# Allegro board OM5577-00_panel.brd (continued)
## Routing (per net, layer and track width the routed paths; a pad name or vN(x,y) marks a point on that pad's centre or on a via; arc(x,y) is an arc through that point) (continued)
A_5_I2C_SCL: length 42.9
  IS1 w0.15: v3(216.2,175.8) 216.2,175.65 217.2,174.65 220.65,174.65 v2(221.2,174.1)
  IS2 w0.5: A_5_TB3.2 197.66,178.24 198.6,177.3 198.6,176.05 201.3,173.35 220.45,173.35 v2(221.2,174.1) 226.9,174.1 229.01,176.21 A_5_TB2.2
A_5_I2C_SDA: length 39
  TOP w0.2: v2(217.3,175.4) 217.3,175.6 216.6,176.3 A_5_U1.C1
  IS2 w0.5: A_5_TB3.3 198.57,180.78 204.1,175.25 210.7,175.25 210.95,175.5 217.2,175.5 v2(217.3,175.4) 219.5,175.4 220,174.9 223.55,174.9 227.4,178.75 A_5_TB2.3
A_5_IRQ: length 39.8
  TOP w0.2: v2(217.3,176.6) 217.3,176.5 217,176.8 A_5_U1.D1
  IS2 w0.5: A_5_TB3.4 198.63,183.32 205,176.95 210.8,176.95 211.25,176.5 217.2,176.5 v2(217.3,176.6) 217.4,176.5 219.8,176.5 220.35,175.95 222.5,175.95 227.84,181.29 A_5_TB2.4
A_5_N2189999: length 7.7
  TOP w0.5: A_5_R55.1 A_5_C17.1 A_5_C50.1 217.1,187.8 217.1,186.27 ; A_5_R53.2 A_5_C15.2 217.1,186.27 ; 217.1,186.27 A_5_C54.2
A_5_N2190055: length 7.8
  TOP w0.5: 212.3,186.27 212.3,187.8 A_5_C51.2 A_5_C18.2 A_5_R56.1 ; 212.3,186.27 A_5_C55.2 ; 212.3,186.27 A_5_C16.2 A_5_R54.2
A_5_N2190079: length 6.3
  TOP w0.5: A_5_C54.1 217.15,184.7 ; 217.15,184.7 217.15,183.1 A_5_R1.1 A_5_C13.1 217.04,181.56 A_5_L1.2 ; 217.15,184.7 A_5_C15.1
A_5_N2190159: length 11.7
  TOP w0.5: A_5_TB1.3 210.59,194.2 A_5_R73.1 arc(209.64,191.93) A_5_R56.2 arc(209.04,188.9) 208.95,188.42 A_5_C12.2 A_5_C52.2
A_5_N2190199: length 11.7
  TOP w0.5: A_5_C53.2 A_5_C11.2 220.45,188.42 arc(220.36,188.9) A_5_R55.2 arc(219.76,191.93) A_5_R75.1 218.81,194.2 A_5_TB1.1
A_5_N2190513: length 6.3
  TOP w0.5: 212.25,184.7 A_5_C16.1 ; 212.25,184.7 212.25,183.2 A_5_R2.2 212.37,181.65 A_5_C14.2 212.36,181.54 A_5_L2.2 ; 212.25,184.7 A_5_C55.1
A_5_N2190991: length 583.3
  TOP w0.5: A_5_L104.1 234.5,194.7 234.5,234.2 216.3,234.2 v2(216.3,234.15) ; A_5_L104.2 195,194.7 195,234.2 214.95,234.2 215.95,233.3 233.75,233.3 233.75,195.6 v2(214.7,195.6) ; v2(216.3,232.4) 233,232.4 233,196.5 214.45,196.5 213.45,195.6 195.75,195.6 195.75,233.3 v2(214.7,233.3) ; v2(214.7,231.5) 197.25,231.5 197.25,197.4 232.25,197.4 232.25,231.5 216.05,231.5 215.05,232.4 196.5,232.4 196.5,196.5 v2(213.1,196.5)
  BOTTOM w0.5: v2(214.7,233.3) v2(216.3,234.15) ; v2(216.3,232.4) v2(214.7,231.5) ; v2(214.7,195.6) v2(213.1,196.5)
A_5_N2198580: length 7.5
  TOP w0.2: A_5_R24.2 219.21,174.67 ; 219.21,174.67 A_5_R23.1 ; 219.21,174.67 219.24,174.7 219.7,174.7 220.1,174.3 v2(220.1,174.1)
  IS1 w0.15: v2(220.1,174.1) 217.25,174.1 215.7,175.65 v3(215.7,175.8)
A_5_N2222470: length 3.3
  TOP w0.5: A_5_R54.1 210.7,184.7 210.7,183.2 A_5_R2.1 A_5_C20.2
A_5_N2227379: length 3.3
  TOP w0.5: A_5_C19.2 A_5_R1.2 218.7,183.1 218.7,184.7 A_5_R53.1
A_5_N2256986: length 4.6
  TOP w0.25: A_5_Y1.3 215.22,172.28 215.5,172.55 215.65,172.55 215.95,172.85 216.29,172.85 A_5_C57.1 216.45,173.65 215.75,174.35 215.45,174.35 215.2,174.6 A_5_U1.A3
A_5_N2256988: length 4.4
  TOP w0.25: v2(214.18,174.53) 214.18,173.57 214.11,173.51 A_5_C56.1
  IS1 w0.25: v2(214.18,174.53) 214.7,175.05 214.7,175.65 215.2,176.15 v3(215.2,176.3)
A_5_N2257197: length 1.7
  TOP w0.2: A_5_U1.A1 216.99,174.51 A_5_R32.2
A_5_N2257995: length 4.2
  TOP w0.25: v2(212.7,174.7) 212.45,174.45 212.06,174.45 A_5_C22.1 A_5_C1.1
  IS1 w0.25: v3(213.7,176.3) 213.3,176.3 212.7,175.7 v2(212.7,174.7)
A_5_N2259746: length 5
  TOP w0.25: A_5_U1.E7 A_5_C7.1 211.91,177.89 211.8,178 209.14,178 A_5_C10.1
A_5_N2259753: length 1.5
  TOP w0.25: A_5_U1.D7 212.75,176.8 212.35,176.4 212.01,176.4 A_5_C8.1
A_5_N2259760: length 1.9
  TOP w0.25: A_5_C6.1 212.35,178.7 212.55,178.5 212.55,178.1 212.85,177.8 A_5_U1.F7
A_5_PVDD: length 62.1
  TOP w0.2: A_5_R23.2 A_5_C3.1
  TOP w0.25: A_5_U1.G1 216.5,178.3 216.9,178.7 A_5_C21.1 A_5_C9.1 ; A_5_U1.C7 212.95,176.3 212.65,176 212.65,175.6 212.35,175.3 A_5_C2.1
  TOP w0.3: A_5_U1.G2 A_5_U1.G1
  TOP w0.5: v2(222.35,172.9) 222.35,176.7 221.35,177.7 v2(220.7,177.7)
  IS1 w0.25: v3(215.2,176.8) 216.6,176.8 216.99,177.19 217.54,177.19 217.88,176.84 217.88,176.76 217.95,176.7 v3(218.05,176.7) v3(218.35,176.7)
  IS1 w0.3: v3(218.35,176.7) 218.35,177.4 218.05,177.7 v3(217.65,177.7) v3(217.35,177.7) ; v2(209.05,171.65) 209.05,174.9 209.65,175.5 v3(211.75,175.5) v3(211.75,175.1)
  IS1 w0.5: v2(220.7,177.7) 220.55,177.7 219.55,176.7 v3(218.35,176.7)
  IS2 w0.5: A_5_TB3.1 200.85,171.65 v2(209.05,171.65) 221.1,171.65 v2(222.35,172.9) 229.16,172.9 A_5_TB2.1
A_5_RXN: length 7.5
  TOP w0.5: A_5_C20.1 210.16,180.11 209.66,179.61 209.66,179.55 v2(209.66,179.55)
  IS1 w0.15: v2(209.66,179.55) 209.66,179.05 210.96,177.75 213.13,177.75 213.58,178.2 214,178.2 214.2,178 v3(214.2,177.8)
A_5_RXP: length 9
  TOP w0.5: v2(219.85,179.6) 219.39,180.06 218.6,180.06
  IS1 w0.15: v2(219.85,179.6) 218.95,178.7 216.4,178.7 215.9,178.2 214.95,178.2 214.7,177.95 214.7,177.6 214.5,177.4 213.9,177.4 213.7,177.6 v3(213.7,177.8)
A_5_TX1: length 1.8
  TOP w0.2: A_5_U1.G3 215.46,178.86
  TOP w0.25: 215.46,178.86 215.47,179.25
  TOP w0.5: 215.47,179.25 A_5_L1.1
A_5_TX2: length 1.8
  TOP w0.2: A_5_U1.G5 213.94,178.86
  TOP w0.25: 213.94,178.86 213.93,179.25
  TOP w0.5: 213.93,179.25 A_5_L2.1
A_5_VEN: length 44.7
  TOP w0.2: A_5_U1.E1 216.5,177.3 216.75,177.55 v3(216.75,177.8)
  IS1 w0.2: v2(221.15,178.85) 220.6,178.3 217.25,178.3 v3(216.75,177.8)
  IS2 w0.5: A_5_TB2.5 228.23,183.83 223.25,178.85 v2(221.15,178.85) 220.75,178.45 219.1,178.45 218.45,177.8 211.85,177.8 211.2,178.45 205.75,178.45 198.34,185.86 A_5_TB3.5
A_6_ANT1: length 13.9
  TOP w0.2: A_6_U1.G7 260.43,178.3 v3(260.43,178.32)
  TOP w0.5: v2(268.95,183.05) 269.2,183.3 A_6_C53.1 A_6_C11.1
  IS1 w0.15: v2(268.95,183.05) 268.95,182.75 265.25,179.05 263.4,179.05 262.85,178.5 260.61,178.5 v3(260.43,178.32)
A_6_ANT2: length 11.5
  TOP w0.2: A_6_U1.G6 260.9,178.35 260.9,178.5 260.4,179 v3(260.2,179)
  TOP w0.5: v2(254.95,183.05) 254.7,183.3 A_6_C52.1 A_6_C12.1
  IS1 w0.15: v2(254.95,183.05) 254.95,182.8 258.75,179 v3(260.2,179)
A_6_GND: length 200.9
  TOP w0.2: v3(263.15,174.85) v3(264.1,173.9) 264.51,173.49 A_6_R32.1 ; v2(261.95,179.05) 261.95,181.6
  TOP w0.3: 246.22,176.8 A_6_SH1.1 ; A_6_SH1.1 247.35,178.43 ; A_6_SH1.1 247.35,175.17 ; A_6_SH1.1 248.48,176.8 ; A_6_C10.2 256.93,176.79 ; A_6_C10.2 256.2,176.11 ; A_6_C10.2 255.47,176.79 ; 249.92,191.9 A_6_SH1.7 ; A_6_SH1.7 253.18,191.9 ; A_6_SH1.7 251.55,190.77 ; A_6_U1.G4 v2(261.95,179.05) ; 264.25,190.77 A_6_SH1.6 ; A_6_SH1.6 265.88,191.9 ; A_6_SH1.6 262.62,191.9 ; 242.67,188.4 A_6_TB3.6 ; A_6_TB3.6 244.05,189.78 ; A_6_TB3.6 245.43,188.4 ; A_6_SH1.4 275.08,175.9 ; A_6_SH1.4 273.95,174.27 ; A_6_SH1.4 273.95,177.53 ; A_6_SH1.4 272.82,175.9 ; 273.95,186.97 A_6_SH1.5 ; A_6_SH1.5 273.95,190.23 ; A_6_SH1.5 275.08,188.6 ; A_6_SH1.5 272.82,188.6 ; 258.14,172.57 A_6_C1.2 257.46,173.3 ; A_6_SH1.8 248.48,189.5 ; A_6_SH1.8 247.35,191.13 ; A_6_SH1.8 246.22,189.5 ; A_6_SH1.8 247.35,187.87 ; 265.53,173.49 A_6_R32.1 264.8,172.81 ; A_6_C13.2 262.68,182.49 ; 267.14,176.7 A_6_C3.2 266.46,177.43 ; 260.25,171.81 A_6_C56.2 259.52,172.49 ; A_6_C9.2 266.44,177.7 ; A_6_C14.1 261.25,182.49 ; A_6_SH1.2 255.48,170.3 ; A_6_SH1.2 252.22,170.3 ; A_6_SH1.2 253.85,171.43 ; 264.92,170.3 A_6_SH1.3 ; A_6_SH1.3 268.18,170.3 ; A_6_SH1.3 266.55,171.43 ; 264.43,171.99 A_6_C57.2 263.7,171.31 ; 257.46,174.3 A_6_C22.2 ; 278.56,186.37 A_6_TB2.6 275.8,186.37 ; 257.46,177.3 A_6_C7.2 ; A_6_C21.2 266.44,178.7 ; 257.46,178.7 A_6_C6.2 ; 265.72,173.64 A_6_R24.1 266.45,172.96 ; 261.43,171.42 A_6_Y1.2 ; v3(261.95,176.3) A_6_U1.D4 ; 257.46,176.3 A_6_C8.2 ; 257.46,175.3 A_6_C2.2
  TOP w0.4: 261.95,187.8 261.95,186.7
  TOP w0.5: A_6_C18.1 A_6_C17.2 ; A_6_C18.1 A_6_C51.1 A_6_C50.2 A_6_C17.2 ; A_6_C18.1 261.25,190.6 ; A_6_C17.2 262.68,190.6 ; A_6_C14.1 A_6_C13.2
  IS1 w0.3: A_6_SH1.6 265.38,191.9 ; A_6_SH1.6 264.25,190.77 ; A_6_SH1.6 263.12,191.9 ; 275.85,186.37 A_6_TB2.6 278.51,186.37 ; A_6_SH1.4 275.08,175.9 ; A_6_SH1.4 273.95,177.03 ; A_6_SH1.4 273.95,174.77 ; A_6_SH1.4 272.82,175.9 ; 246.22,189.5 A_6_SH1.8 ; A_6_SH1.8 248.48,189.5 ; A_6_SH1.8 247.35,188.37 ; A_6_SH1.8 247.35,190.63 ; 273.95,187.47 A_6_SH1.5 ; A_6_SH1.5 272.82,188.6 ; A_6_SH1.5 273.95,189.73 ; A_6_SH1.5 275.08,188.6 ; A_6_SH1.1 247.35,177.93 ; A_6_SH1.1 247.35,175.67 ; A_6_SH1.1 248.48,176.8 ; A_6_SH1.1 246.22,176.8 ; A_6_SH1.2 253.85,171.43 ; A_6_SH1.2 254.98,170.3 ; A_6_SH1.2 252.72,170.3 ; A_6_SH1.3 266.55,171.43 ; A_6_SH1.3 265.42,170.3 ; A_6_SH1.3 267.68,170.3 ; 250.42,191.9 A_6_SH1.7 ; A_6_SH1.7 252.68,191.9 ; A_6_SH1.7 251.55,190.77 ; A_6_TB3.6 245.38,188.4 ; A_6_TB3.6 244.05,189.73 ; A_6_TB3.6 242.72,188.4
  IS2 w0.3: 278.51,186.37 A_6_TB2.6 275.85,186.37 ; A_6_SH1.5 273.95,189.73 ; A_6_SH1.5 275.08,188.6 ; A_6_SH1.5 272.82,188.6 ; A_6_SH1.5 273.95,187.47 ; 252.72,170.3 A_6_SH1.2 254.98,170.3 ; 251.55,190.77 A_6_SH1.7 ; A_6_SH1.7 252.68,191.9 ; A_6_SH1.7 250.42,191.9 ; 264.25,190.77 A_6_SH1.6 ; A_6_SH1.6 265.38,191.9 ; A_6_SH1.6 263.12,191.9 ; 272.82,175.9 A_6_SH1.4 ; A_6_SH1.4 273.95,174.77 ; A_6_SH1.4 275.08,175.9 ; A_6_SH1.4 273.95,177.03 ; 247.35,175.67 A_6_SH1.1 ; A_6_SH1.1 248.48,176.8 ; A_6_SH1.1 247.35,177.93 ; 265.42,170.3 A_6_SH1.3 267.68,170.3 ; 246.22,189.5 A_6_SH1.8 ; A_6_SH1.8 247.35,188.37 ; A_6_SH1.8 248.48,189.5 ; A_6_SH1.8 247.35,190.63 ; A_6_TB3.6 245.38,188.4 ; A_6_TB3.6 242.72,188.4 ; A_6_TB3.6 244.05,189.73
  BOTTOM w0.3: 247.35,175.17 A_6_SH1.1 ; A_6_SH1.1 246.22,176.8 ; A_6_SH1.1 247.35,178.43 ; A_6_SH1.1 248.48,176.8 ; A_6_SH1.3 268.18,170.3 ; A_6_SH1.3 266.55,171.43 ; A_6_SH1.3 264.92,170.3 ; 272.82,175.9 A_6_SH1.4 ; A_6_SH1.4 275.08,175.9 ; A_6_SH1.4 273.95,177.53 ; A_6_SH1.4 273.95,174.27 ; 272.82,188.6 A_6_SH1.5 ; A_6_SH1.5 275.08,188.6 ; A_6_SH1.5 273.95,186.97 ; A_6_SH1.5 273.95,190.23 ; A_6_TB3.6 244.05,189.78 ; A_6_TB3.6 245.43,188.4 ; A_6_TB3.6 242.67,188.4 ; A_6_SH1.7 253.18,191.9 ; A_6_SH1.7 251.55,190.77 ; A_6_SH1.7 249.92,191.9 ; A_6_SH1.2 253.85,171.43 ; A_6_SH1.2 252.22,170.3 ; A_6_SH1.2 255.48,170.3 ; A_6_SH1.8 247.35,191.13 ; A_6_SH1.8 248.48,189.5 ; A_6_SH1.8 247.35,187.87 ; A_6_SH1.8 246.22,189.5 ; A_6_SH1.6 265.88,191.9 ; A_6_SH1.6 264.25,190.77 ; A_6_SH1.6 262.62,191.9 ; 275.8,186.37 A_6_TB2.6 278.56,186.37
  vias: v2(242.35,189.85) v2(242.35,187.35) v2(242.35,184.85) v2(242.35,182.35) v2(242.35,179.85) v2(242.35,177.35) v2(242.35,174.85) v2(242.35,172.35) v2(242.35,169.85) v2(243.75,173.5) v2(243.75,171) v2(244.85,169.85) v2(244.9,172.25) v2(245.65,190.35) v2(245.85,186.75) v2(245.85,184.4) v2(245.85,182) v2(245.85,179.05) v2(245.85,175) v2(246.05,170.9) v2(246.2,192.55) v2(247.35,191.85) v2(247.35,187.3) v2(247.35,185.5) v2(247.35,183) v2(247.35,180.55) v2(247.35,173.5) v2(247.35,170.35) v2(248.2,192.6) v2(248.7,174.65) v2(248.9,190.5) v2(248.9,188) v2(248.9,185.5) v2(248.9,183.6) v2(249.4,172.55) v2(249.5,178.5) v2(249.7,175.8) v2(249.65,170.3) v2(249.85,192.6) v2(249.85,180.5) v2(250.3,189.3) v2(250.3,186.8) v2(250.3,184.3) v2(250.65,174.3) v2(251.4,190.5) v2(251.4,188) v2(251.4,185.5) v2(251.4,183) v2(251.4,181.1) v2(251.4,170.3) v2(251.75,176.15) v2(251.8,172.5) v2(252.15,178.15) v2(252.65,189.25) v2(252.65,186.75) v2(252.65,184.25) v2(252.65,181.75) v2(252.85,179.7) v2(253,174.3) v2(253.25,192.65) v2(253.5,187.55) v2(253.5,185.45) v2(253.7,189.3) v2(253.9,183) v2(253.9,180.5) v2(254.45,176) v2(254.45,174.3) v2(254.55,192.6) v2(254.55,172.5) v2(254.7,177.7) v2(255.2,189.05) v2(255.25,187.45) v2(255.2,181.6) v2(255.25,179.55) v2(255.65,190.7) v2(255.8,170.3) v2(255.9,183.5) v2(256.05,192.65) v2(256.4,180.5) v2(256.85,181.75) v2(256.9,183.5) v2(257.1,174.3) v2(257.05,172.5) v2(257.15,187.8) v2(257.2,176.2) v2(257.65,190.6) v2(258.15,192.55) v2(258.15,172.4) v2(258.4,170.25) v2(258.5,187.8) v2(259.45,191.9) v2(259.95,190.55) v2(260.5,192.6) v2(260.8,170.3) v2(261.25,183.55) v2(261.25,182.7) v2(261.85,191.9) v2(262,190.45) v2(262.55,192.65) v2(262.65,183.55) v2(262.65,182.7) v2(263.35,170.3) v2(264.4,190.5) v2(264.8,172.55) v2(265.45,187.75) v2(265.8,192.65) v2(266.3,190.5) v2(266.7,177.7) v2(266.75,187.75) v2(267,183.5) v2(267.05,181.7) v2(267.05,172.6) v2(267.85,192.6) v2(267.9,180.5) v2(267.9,176.7) v2(268,183.5) v2(268.25,190.5) v2(268.5,173) v2(268.65,189.15) v2(268.65,187.5) v2(268.75,191.9) v2(268.9,181.45) v2(269.7,171.4) v2(269.85,192.6) v2(269.95,177.85) v2(270,183) v2(270,180.5) v2(270.2,189.7) v2(270.3,186.7) v2(270.3,184.6) v2(270.65,170.3) v2(270.75,175.9) v2(271.3,191.9) v2(271.45,190.65) v2(271.45,188.7) v2(271.45,186.2) v2(271.45,183.7) v2(271.45,181.2) v2(271.9,174.85) v2(272.25,179.55) v2(272.2,171.4) v2(272.7,189.95) v2(272.7,187.45) v2(272.7,184.95) v2(272.7,182.45) v2(272.8,192.65) v2(273.9,191.85) v2(273.95,186.3) v2(273.95,183.7) v2(273.95,181.2) v2(273.95,179.1) v2(273.95,172.1) v2(273.95,170.3) v2(275.4,192.65) v2(275.4,190.15) v2(275.4,187.65) v2(275.4,185.15) v2(275.4,182.4) v2(275.4,180) v2(275.45,177.2) v2(275.45,173.8) v2(276.1,171.9) v2(276.1,169.85) v2(278.6,169.85) v2(279.15,192.65) v2(279.15,190.15) v2(279.15,187.65) v2(279.15,185.15) v2(279.15,182.65) v2(279.15,180.15) v2(279.05,177.65) v2(279.05,175.15) v2(279.15,172.95) v2(280.4,191.4) v2(280.4,188.9) v2(280.4,186.4) v2(280.4,183.9) v2(280.4,181.4) v2(280.4,178.9) v2(281.65,192.65) v2(281.65,190.15) v2(281.65,187.65) v2(281.65,185.15) v2(281.65,182.65) v2(281.65,180.15) v2(281.65,177.65) v2(281.65,175.15) v2(281.65,172.65) v3(260.95,176.8) v3(260.95,175.8) v3(261.2,172.4) v3(261.2,171.95) v3(261.45,175.8) v3(261.65,172.4) v3(261.65,171.95) v3(262.25,173.85) v3(262.25,173.3) v3(262.45,177.8) v3(262.7,173.85) v3(262.7,173.3) v3(262.95,177.3) v3(262.95,176.3)
A_6_I2C_SCL: length 42.9
  IS1 w0.15: v2(268.45,174.1) 267.9,174.65 264.45,174.65 263.45,175.65 v3(263.45,175.8)
  IS2 w0.5: A_6_TB3.2 244.91,178.24 245.85,177.3 245.85,176.05 248.55,173.35 267.7,173.35 v2(268.45,174.1) 274.15,174.1 276.26,176.21 A_6_TB2.2
A_6_I2C_SDA: length 39
  TOP w0.2: A_6_U1.C1 263.85,176.3 264.55,175.6 v2(264.55,175.4)
  IS2 w0.5: A_6_TB2.3 274.65,178.75 270.8,174.9 267.25,174.9 266.75,175.4 v2(264.55,175.4) 264.45,175.5 258.2,175.5 257.95,175.25 251.35,175.25 245.82,180.78 A_6_TB3.3
A_6_IRQ: length 39.8
  TOP w0.2: v2(264.55,176.6) 264.55,176.5 264.25,176.8 A_6_U1.D1
  IS2 w0.5: A_6_TB2.4 275.09,181.29 269.75,175.95 267.6,175.95 267.05,176.5 264.65,176.5 v2(264.55,176.6) 264.45,176.5 258.5,176.5 258.05,176.95 252.25,176.95 245.88,183.32 A_6_TB3.4
A_6_N2189999: length 7.7
  TOP w0.5: 264.35,186.27 A_6_C15.2 A_6_R53.2 ; 264.35,186.27 A_6_C54.2 ; 264.35,186.27 264.35,187.8 A_6_C50.1 A_6_C17.1 265.76,189.3
A_6_N2190055: length 7.8
  TOP w0.5: A_6_R56.1 A_6_C18.2 A_6_C51.2 259.55,187.8 259.55,186.27 ; A_6_R54.2 A_6_C16.2 259.55,186.27 ; 259.55,186.27 A_6_C55.2
A_6_N2190079: length 6.3
  TOP w0.5: A_6_C54.1 264.4,184.7 ; 264.4,184.7 A_6_C15.1 ; 264.4,184.7 264.4,183.1 A_6_R1.1 A_6_C13.1 264.29,181.56 A_6_L1.2
A_6_N2190159: length 11.7
  TOP w0.5: A_6_TB1.3 257.84,194.2 257.84,194.4 arc(256.89,191.93) A_6_R56.2 arc(256.29,188.9) 256.2,188.42 A_6_C12.2 A_6_C52.2
A_6_N2190199: length 11.7
  TOP w0.5: A_6_C53.2 A_6_C11.2 267.7,188.42 arc(267.61,188.9) A_6_R55.2 arc(267.01,191.93) A_6_R75.1 266.06,194.2 A_6_TB1.1
A_6_N2190513: length 6.3
  TOP w0.5: A_6_C55.1 259.5,184.7 ; 259.5,184.7 259.5,183.2 A_6_R2.2 259.62,181.65 A_6_C14.2 259.61,181.54 A_6_L2.2 ; 259.5,184.7 A_6_C16.1
A_6_N2190991: length 583.3
  TOP w0.5: v2(261.95,233.3) 243,233.3 243,195.6 260.7,195.6 261.7,196.5 280.25,196.5 280.25,232.4 v2(263.55,232.4) ; v2(261.95,231.5) 244.5,231.5 244.5,197.4 279.5,197.4 279.5,231.5 263.3,231.5 262.3,232.4 243.75,232.4 243.75,196.5 v2(260.35,196.5) ; v2(261.95,195.6) 281,195.6 281,233.3 263.2,233.3 262.2,234.2 242.25,234.2 242.25,194.7 A_6_L104.2 ; v2(263.55,234.15) 263.55,234.2 281.75,234.2 281.75,194.7 A_6_L104.1
  BOTTOM w0.5: v2(261.95,233.3) v2(263.55,234.15) ; v2(261.95,195.6) v2(260.35,196.5) ; v2(263.55,232.4) v2(261.95,231.5)
A_6_N2198580: length 7.5
  TOP w0.2: A_6_R24.2 266.46,174.67 ; 266.46,174.67 A_6_R23.1 ; 266.46,174.67 266.49,174.7 266.95,174.7 267.35,174.3 v2(267.35,174.1)
  IS1 w0.15: v3(262.95,175.8) 262.95,175.65 264.5,174.1 v2(267.35,174.1)
A_6_N2222470: length 3.3
  TOP w0.5: A_6_C20.2 A_6_R2.1 257.95,183.2 257.95,184.7 A_6_R54.1
A_6_N2227379: length 3.3
  TOP w0.5: A_6_C19.2 A_6_R1.2 265.95,183.1 265.95,184.7 A_6_R53.1
A_6_N2256986: length 4.6
  TOP w0.25: A_6_U1.A3 262.45,174.6 262.7,174.35 263,174.35 263.7,173.65 A_6_C57.1 263.54,172.85 263.2,172.85 262.9,172.55 262.75,172.55 262.48,172.28 262.48,172.22
A_6_N2256988: length 4.4
  TOP w0.25: A_6_C56.1 261.36,173.51 A_6_Y1.1 v2(261.43,174.53)
  IS1 w0.25: v2(261.43,174.53) 261.95,175.05 261.95,175.65 262.45,176.15 v3(262.45,176.3)
A_6_N2257197: length 1.7
  TOP w0.2: A_6_U1.A1 264.24,174.51 A_6_R32.2
A_6_N2257995: length 4.2
  TOP w0.25: A_6_C1.1 A_6_C22.1 259.31,174.45 259.7,174.45 v2(259.95,174.7)
  IS1 w0.25: v3(260.95,176.3) 260.55,176.3 259.95,175.7 v2(259.95,174.7)
A_6_N2259746: length 5
  TOP w0.25: A_6_U1.E7 A_6_C7.1 259.16,177.89 259.05,178 256.39,178 A_6_C10.1
A_6_N2259753: length 1.5
  TOP w0.25: A_6_C8.1 259.26,176.4 259.6,176.4 260,176.8 A_6_U1.D7
A_6_N2259760: length 1.9
  TOP w0.25: A_6_C6.1 259.6,178.7 259.8,178.5 259.8,178.1 260.1,177.8 A_6_U1.F7
A_6_PVDD: length 62.1
  TOP w0.2: A_6_R23.2 A_6_C3.1
  TOP w0.25: A_6_C2.1 259.6,175.3 259.9,175.6 259.9,176 260.2,176.3 A_6_U1.C7 ; A_6_U1.G1 263.75,178.3 264.15,178.7 A_6_C21.1 A_6_C9.1
  TOP w0.3: A_6_U1.G2 A_6_U1.G1
  TOP w0.5: v2(269.6,172.9) 269.6,176.7 268.6,177.7 v2(267.95,177.7)
  IS1 w0.25: v3(262.45,176.8) 263.85,176.8 264.24,177.19 264.79,177.19 265.13,176.84 265.13,176.76 265.2,176.7 v3(265.3,176.7) v3(265.6,176.7)
  IS1 w0.3: v3(259,175.1) v3(259,175.5) 256.9,175.5 256.3,174.9 v2(256.3,171.65) ; v3(265.6,176.7) 265.6,177.4 265.3,177.7 v3(264.9,177.7) v3(264.6,177.7)
  IS1 w0.5: v2(267.95,177.7) 267.8,177.7 266.8,176.7 v3(265.6,176.7)
  IS2 w0.5: A_6_TB2.1 276.41,172.9 v2(269.6,172.9) 268.35,171.65 v2(256.3,171.65) 248.1,171.65 A_6_TB3.1
A_6_RXN: length 7.5
  TOP w0.5: v2(256.91,179.55) 256.91,179.55 256.91,179.61 257.41,180.11 A_6_C20.1
  IS1 w0.15: v2(256.91,179.55) 256.91,179.05 258.21,177.75 260.38,177.75 260.83,178.2 261.25,178.2 261.45,178 v3(261.45,177.8)
A_6_RXP: length 9
  TOP w0.5: 265.85,180.06 266.64,180.06 v2(267.1,179.6)
  IS1 w0.15: v3(260.95,177.8) 260.95,177.6 261.15,177.4 261.75,177.4 261.95,177.6 261.95,177.95 262.2,178.2 263.15,178.2 263.65,178.7 266.2,178.7 v2(267.1,179.6)
A_6_TX1: length 1.8
  TOP w0.2: A_6_U1.G3 262.71,178.86
  TOP w0.25: 262.71,178.86 262.72,179.25
  TOP w0.5: 262.72,179.25 A_6_L1.1
A_6_TX2: length 1.8
  TOP w0.2: A_6_U1.G5 261.19,178.86
  TOP w0.25: 261.19,178.86 261.18,179.25
  TOP w0.5: 261.18,179.25 A_6_L2.1
A_6_VEN: length 44.7
  TOP w0.2: v3(264,177.8) 264,177.55 263.75,177.3 A_6_U1.E1
  IS1 w0.2: v2(268.4,178.85) 267.85,178.3 264.5,178.3 v3(264,177.8)
  IS2 w0.5: A_6_TB2.5 275.48,183.83 270.5,178.85 v2(268.4,178.85) 268,178.45 266.35,178.45 265.7,177.8 259.1,177.8 258.45,178.45 253,178.45 245.59,185.86 A_6_TB3.5
B_1_GND_2272419: length 138.5
  TOP w0.3: B_1_J9.C45 53.77,64.22 ; B_1_J9.C45 52.65,63.1 ; B_1_J9.C45 52.65,65.35 ; 4.39,7.22 B_1_J8.C1 ; B_1_J8.C1 4.39,9.47 ; B_1_J8.C1 3.26,8.34 ; B_1_J8.C1 5.51,8.34 ; B_1_J9.C1 53.77,8.34 ; B_1_J9.C1 51.52,8.34 ; B_1_J9.C1 52.65,9.47 ; B_1_J9.C1 52.65,7.22 ; 0.72,8.34 B_1_J8.C2 ; B_1_J8.C2 1.85,9.47 ; B_1_J8.C2 1.85,7.22 ; B_1_J8.C2 2.97,8.34 ; B_1_J9.C43 52.65,62.81 ; B_1_J9.C43 53.77,61.69 ; B_1_J9.C43 52.65,60.56 ; B_1_J9.C2 50.11,9.47 ; B_1_J9.C2 48.98,8.34 ; B_1_J9.C2 51.23,8.34 ; B_1_J9.C2 50.11,7.22 ; 43.81,26.39 B_1_TB9.6 41.05,26.39 ; 7.92,28.42 B_1_TB8.6 10.68,28.42
  TOP w0.5: B_1_J9.C44 B_1_J9.C43 ; B_1_J9.C46 B_1_J9.C45
  IS1 w0.3: 41.1,26.39 B_1_TB9.6 43.76,26.39 ; 52.65,63.15 B_1_J9.C45 ; B_1_J9.C45 53.72,64.22 ; B_1_J9.C45 52.65,65.3 ; B_1_J8.C1 5.46,8.34 ; B_1_J8.C1 4.39,7.27 ; B_1_J8.C1 4.39,9.42 ; B_1_J8.C1 3.31,8.34 ; 52.65,60.61 B_1_J9.C43 ; B_1_J9.C43 53.72,61.69 ; B_1_J9.C43 52.65,62.76 ; 7.97,28.42 B_1_TB8.6 10.63,28.42 ; 1.85,7.27 B_1_J8.C2 ; B_1_J8.C2 1.85,9.42 ; B_1_J8.C2 0.77,8.34 ; B_1_J8.C2 2.92,8.34 ; 50.11,7.27 B_1_J9.C2 ; B_1_J9.C2 51.18,8.34 ; B_1_J9.C2 49.03,8.34 ; B_1_J9.C2 50.11,9.42 ; B_1_J9.C1 53.72,8.34 ; B_1_J9.C1 51.57,8.34 ; B_1_J9.C1 52.65,7.27 ; B_1_J9.C1 52.65,9.42
  IS1 w0.5: B_1_J9.C46 B_1_J9.C45 ; B_1_J9.C44 B_1_J9.C43
  IS2 w0.3: 49.03,8.34 B_1_J9.C2 ; B_1_J9.C2 51.18,8.34 ; B_1_J9.C2 50.11,9.42 ; B_1_J9.C2 50.11,7.27 ; 1.85,7.27 B_1_J8.C2 ; B_1_J8.C2 2.92,8.34 ; B_1_J8.C2 1.85,9.42 ; B_1_J8.C2 0.77,8.34 ; 43.76,26.39 B_1_TB9.6 41.1,26.39 ; B_1_J8.C1 5.46,8.34 ; B_1_J8.C1 3.31,8.34 ; B_1_J8.C1 4.39,7.27 ; B_1_J8.C1 4.39,9.42 ; 52.65,60.61 B_1_J9.C43 ; B_1_J9.C43 53.72,61.69 ; B_1_J9.C43 52.65,62.76 ; B_1_J9.C45 52.65,65.3 ; B_1_J9.C45 52.65,63.15 ; B_1_J9.C45 53.72,64.22 ; B_1_J9.C1 52.65,9.42 ; B_1_J9.C1 53.72,8.34 ; B_1_J9.C1 52.65,7.27 ; B_1_J9.C1 51.57,8.34 ; 7.97,28.42 B_1_TB8.6 10.63,28.42
  IS2 w0.5: B_1_J9.C44 B_1_J9.C43 ; B_1_J9.C46 B_1_J9.C45
  BOTTOM w0.3: 51.52,8.34 B_1_J9.C1 ; B_1_J9.C1 52.65,9.47 ; B_1_J9.C1 53.77,8.34 ; B_1_J9.C1 52.65,7.22 ; 50.11,7.22 B_1_J9.C2 ; B_1_J9.C2 50.11,9.47 ; B_1_J9.C2 48.98,8.34 ; B_1_J9.C2 51.23,8.34 ; 4.39,7.22 B_1_J8.C1 ; B_1_J8.C1 4.39,9.47 ; B_1_J8.C1 3.26,8.34 ; B_1_J8.C1 5.51,8.34 ; B_1_J9.C43 53.77,61.69 ; B_1_J9.C43 52.65,60.56 ; B_1_J9.C43 52.65,62.81 ; 41.05,26.39 B_1_TB9.6 43.81,26.39 ; 0.72,8.34 B_1_J8.C2 ; B_1_J8.C2 1.85,9.47 ; B_1_J8.C2 2.97,8.34 ; B_1_J8.C2 1.85,7.22 ; 10.68,28.42 B_1_TB8.6 7.92,28.42 ; B_1_J9.C45 52.65,65.35 ; B_1_J9.C45 53.77,64.22 ; B_1_J9.C45 52.65,63.1
  BOTTOM w0.5: B_1_J9.C44 B_1_J9.C43 ; B_1_J9.C46 B_1_J9.C45
  vias: v2(1.45,68.05) v2(53.2,67.9)
B_1_I2C_SCL_2272419: length 20.9
  BOTTOM w0.3: B_1_J9.C19 52.65,31.1 51.55,30 48.7,30 47.65,28.95 47.65,21.45 B_1_TB9.2
B_1_I2C_SDA_2272319: length 16.8
  BOTTOM w0.3: B_1_J9.C20 48.01,31.21 46.25,29.45 46.25,22.59 B_1_TB9.3
B_1_IRQ_2273337: length 20.6
  BOTTOM w0.3: B_1_J8.C26 3.07,37.6 5.3,37.6 5.95,36.95 5.95,25.45 8.06,23.34 B_1_TB8.4
B_1_VBAT_PVDD: length 11.4
  BOTTOM w0.5: B_1_TB9.1 45.23,10.88 B_1_J9.C4 B_1_J9.C3
B_1_VEN_2272419: length 11.4
  IS2 w0.3: B_1_J9.C11 51.39,22.3 43.98,22.3 B_1_TB9.5
B_2_GND_2272419: length 138.5
  TOP w0.3: 106.98,8.34 B_2_J9.C2 ; B_2_J9.C2 108.11,9.47 ; B_2_J9.C2 109.23,8.34 ; B_2_J9.C2 108.11,7.22 ; B_2_J9.C1 111.77,8.34 ; B_2_J9.C1 110.65,9.47 ; B_2_J9.C1 110.65,7.22 ; B_2_J9.C1 109.52,8.34 ; 68.68,28.42 B_2_TB8.6 65.92,28.42 ; 101.81,26.39 B_2_TB9.6 99.05,26.39 ; B_2_J9.C43 110.65,62.81 ; B_2_J9.C43 111.77,61.69 ; B_2_J9.C43 110.65,60.56 ; 58.72,8.34 B_2_J8.C2 ; B_2_J8.C2 59.85,7.22 ; B_2_J8.C2 60.97,8.34 ; B_2_J8.C2 59.85,9.47 ; 61.26,8.34 B_2_J8.C1 ; B_2_J8.C1 63.51,8.34 ; B_2_J8.C1 62.39,7.22 ; B_2_J8.C1 62.39,9.47 ; B_2_J9.C45 111.77,64.22 ; B_2_J9.C45 110.65,63.1 ; B_2_J9.C45 110.65,65.35
  TOP w0.5: B_2_J9.C46 B_2_J9.C45 ; B_2_J9.C44 B_2_J9.C43
  IS1 w0.3: B_2_J9.C1 110.65,9.42 ; B_2_J9.C1 111.72,8.34 ; B_2_J9.C1 109.57,8.34 ; B_2_J9.C1 110.65,7.27 ; 58.77,8.34 B_2_J8.C2 ; B_2_J8.C2 59.85,7.27 ; B_2_J8.C2 60.92,8.34 ; B_2_J8.C2 59.85,9.42 ; B_2_J8.C1 63.46,8.34 ; B_2_J8.C1 62.39,7.27 ; B_2_J8.C1 62.39,9.42 ; B_2_J8.C1 61.31,8.34 ; 107.03,8.34 B_2_J9.C2 ; B_2_J9.C2 109.18,8.34 ; B_2_J9.C2 108.11,7.27 ; B_2_J9.C2 108.11,9.42 ; 110.65,63.15 B_2_J9.C45 ; B_2_J9.C45 111.72,64.22 ; B_2_J9.C45 110.65,65.3 ; 101.76,26.39 B_2_TB9.6 99.1,26.39 ; 68.63,28.42 B_2_TB8.6 65.97,28.42 ; B_2_J9.C43 111.72,61.69 ; B_2_J9.C43 110.65,60.61 ; B_2_J9.C43 110.65,62.76
  IS1 w0.5: B_2_J9.C46 B_2_J9.C45 ; B_2_J9.C44 B_2_J9.C43
  IS2 w0.3: B_2_J9.C1 111.72,8.34 ; B_2_J9.C1 110.65,9.42 ; B_2_J9.C1 109.57,8.34 ; B_2_J9.C1 110.65,7.27 ; B_2_J9.C2 109.18,8.34 ; B_2_J9.C2 107.03,8.34 ; B_2_J9.C2 108.11,9.42 ; B_2_J9.C2 108.11,7.27 ; B_2_J8.C1 62.39,9.42 ; B_2_J8.C1 63.46,8.34 ; B_2_J8.C1 61.31,8.34 ; B_2_J8.C1 62.39,7.27 ; 110.65,60.61 B_2_J9.C43 ; B_2_J9.C43 111.72,61.69 ; B_2_J9.C43 110.65,62.76 ; B_2_J9.C45 111.72,64.22 ; B_2_J9.C45 110.65,63.15 ; B_2_J9.C45 110.65,65.3 ; 101.76,26.39 B_2_TB9.6 99.1,26.39 ; 68.63,28.42 B_2_TB8.6 65.97,28.42 ; B_2_J8.C2 59.85,9.42 ; B_2_J8.C2 60.92,8.34 ; B_2_J8.C2 59.85,7.27 ; B_2_J8.C2 58.77,8.34
  IS2 w0.5: B_2_J9.C44 B_2_J9.C43 ; B_2_J9.C46 B_2_J9.C45
  BOTTOM w0.3: B_2_J8.C2 59.85,9.47 ; B_2_J8.C2 59.85,7.22 ; B_2_J8.C2 60.97,8.34 ; B_2_J8.C2 58.72,8.34 ; B_2_J9.C43 110.65,62.81 ; B_2_J9.C43 110.65,60.56 ; B_2_J9.C43 111.77,61.69 ; 106.98,8.34 B_2_J9.C2 ; B_2_J9.C2 109.23,8.34 ; B_2_J9.C2 108.11,9.47 ; B_2_J9.C2 108.11,7.22 ; B_2_J9.C45 110.65,65.35 ; B_2_J9.C45 111.77,64.22 ; B_2_J9.C45 110.65,63.1 ; B_2_J9.C1 110.65,9.47 ; B_2_J9.C1 111.77,8.34 ; B_2_J9.C1 110.65,7.22 ; B_2_J9.C1 109.52,8.34 ; 101.81,26.39 B_2_TB9.6 99.05,26.39 ; B_2_J8.C1 63.51,8.34 ; B_2_J8.C1 61.26,8.34 ; B_2_J8.C1 62.39,9.47 ; B_2_J8.C1 62.39,7.22 ; 65.92,28.42 B_2_TB8.6 68.68,28.42
  BOTTOM w0.5: B_2_J9.C46 B_2_J9.C45 ; B_2_J9.C44 B_2_J9.C43
  vias: v2(59.45,68.05) v2(111.2,67.9)
B_2_I2C_SCL_2272419: length 20.9
  BOTTOM w0.3: B_2_TB9.2 105.65,21.45 105.65,28.95 106.7,30 109.55,30 110.65,31.1 B_2_J9.C19
B_2_I2C_SDA_2272319: length 16.8
  BOTTOM w0.3: B_2_J9.C20 106,31.21 104.25,29.45 104.25,22.59 B_2_TB9.3
B_2_IRQ_2273337: length 20.6
  BOTTOM w0.3: B_2_J8.C26 61.07,37.6 63.3,37.6 63.95,36.95 63.95,25.45 66.06,23.34 B_2_TB8.4
B_2_VBAT_PVDD: length 11.4
  BOTTOM w0.5: B_2_TB9.1 103.23,10.88 B_2_J9.C4 B_2_J9.C3
B_2_VEN_2272419: length 11.4
  IS2 w0.3: B_2_TB9.5 101.98,22.3 109.39,22.3 B_2_J9.C11
B_3_GND_2272419: length 138.5
  TOP w0.3: 117.85,7.22 B_3_J8.C2 ; B_3_J8.C2 118.97,8.34 ; B_3_J8.C2 116.72,8.34 ; B_3_J8.C2 117.85,9.47 ; B_3_J9.C43 168.65,62.81 ; B_3_J9.C43 169.77,61.69 ; B_3_J9.C43 168.65,60.56 ; B_3_J9.C1 168.65,9.47 ; B_3_J9.C1 169.77,8.34 ; B_3_J9.C1 167.52,8.34 ; B_3_J9.C1 168.65,7.22 ; B_3_J9.C2 167.23,8.34 ; B_3_J9.C2 164.98,8.34 ; B_3_J9.C2 166.11,7.22 ; B_3_J9.C2 166.11,9.47 ; 157.05,26.39 B_3_TB9.6 159.81,26.39 ; B_3_J8.C1 121.51,8.34 ; B_3_J8.C1 120.39,9.47 ; B_3_J8.C1 119.26,8.34 ; B_3_J8.C1 120.39,7.22 ; B_3_J9.C45 168.65,65.35 ; B_3_J9.C45 168.65,63.1 ; B_3_J9.C45 169.77,64.22 ; 126.68,28.42 B_3_TB8.6 123.92,28.42
  TOP w0.5: B_3_J9.C44 B_3_J9.C43 ; B_3_J9.C46 B_3_J9.C45
  IS1 w0.3: B_3_J9.C45 168.65,65.3 ; B_3_J9.C45 169.72,64.22 ; B_3_J9.C45 168.65,63.15 ; B_3_J9.C43 169.72,61.69 ; B_3_J9.C43 168.65,60.61 ; B_3_J9.C43 168.65,62.76 ; 120.39,7.27 B_3_J8.C1 ; B_3_J8.C1 119.31,8.34 ; B_3_J8.C1 121.46,8.34 ; B_3_J8.C1 120.39,9.42 ; 157.1,26.39 B_3_TB9.6 159.76,26.39 ; 165.03,8.34 B_3_J9.C2 ; B_3_J9.C2 166.11,7.27 ; B_3_J9.C2 167.18,8.34 ; B_3_J9.C2 166.11,9.42 ; 123.97,28.42 B_3_TB8.6 126.63,28.42 ; 167.57,8.34 B_3_J9.C1 ; B_3_J9.C1 168.65,9.42 ; B_3_J9.C1 168.65,7.27 ; B_3_J9.C1 169.72,8.34 ; 117.85,7.27 B_3_J8.C2 ; B_3_J8.C2 117.85,9.42 ; B_3_J8.C2 118.92,8.34 ; B_3_J8.C2 116.77,8.34
  IS1 w0.5: B_3_J9.C46 B_3_J9.C45 ; B_3_J9.C44 B_3_J9.C43
  IS2 w0.3: B_3_J9.C43 168.65,62.76 ; B_3_J9.C43 169.72,61.69 ; B_3_J9.C43 168.65,60.61 ; B_3_J9.C2 167.18,8.34 ; B_3_J9.C2 165.03,8.34 ; B_3_J9.C2 166.11,7.27 ; B_3_J9.C2 166.11,9.42 ; B_3_J8.C2 118.92,8.34 ; B_3_J8.C2 117.85,9.42 ; B_3_J8.C2 116.77,8.34 ; B_3_J8.C2 117.85,7.27 ; B_3_J9.C1 168.65,9.42 ; B_3_J9.C1 167.57,8.34 ; B_3_J9.C1 168.65,7.27 ; B_3_J9.C1 169.72,8.34 ; 157.1,26.39 B_3_TB9.6 159.76,26.39 ; 123.97,28.42 B_3_TB8.6 126.63,28.42 ; 119.31,8.34 B_3_J8.C1 ; B_3_J8.C1 121.46,8.34 ; B_3_J8.C1 120.39,9.42 ; B_3_J8.C1 120.39,7.27 ; 168.65,63.15 B_3_J9.C45 ; B_3_J9.C45 169.72,64.22 ; B_3_J9.C45 168.65,65.3
  IS2 w0.5: B_3_J9.C44 B_3_J9.C43 ; B_3_J9.C46 B_3_J9.C45
  BOTTOM w0.3: B_3_J9.C2 166.11,9.47 ; B_3_J9.C2 166.11,7.22 ; B_3_J9.C2 167.23,8.34 ; B_3_J9.C2 164.98,8.34 ; B_3_J9.C45 168.65,65.35 ; B_3_J9.C45 168.65,63.1 ; B_3_J9.C45 169.77,64.22 ; B_3_J9.C43 169.77,61.69 ; B_3_J9.C43 168.65,62.81 ; B_3_J9.C43 168.65,60.56 ; 120.39,7.22 B_3_J8.C1 ; B_3_J8.C1 119.26,8.34 ; B_3_J8.C1 121.51,8.34 ; B_3_J8.C1 120.39,9.47 ; 117.85,7.22 B_3_J8.C2 ; B_3_J8.C2 117.85,9.47 ; B_3_J8.C2 116.72,8.34 ; B_3_J8.C2 118.97,8.34 ; 167.52,8.34 B_3_J9.C1 ; B_3_J9.C1 169.77,8.34 ; B_3_J9.C1 168.65,7.22 ; B_3_J9.C1 168.65,9.47 ; 123.92,28.42 B_3_TB8.6 126.68,28.42 ; 159.81,26.39 B_3_TB9.6 157.05,26.39
  BOTTOM w0.5: B_3_J9.C44 B_3_J9.C43 ; B_3_J9.C46 B_3_J9.C45
  vias: v2(117.45,68.05) v2(169.2,67.9)
B_3_I2C_SCL_2272419: length 20.9
  BOTTOM w0.3: B_3_TB9.2 163.65,21.45 163.65,28.95 164.7,30 167.55,30 168.65,31.1 B_3_J9.C19
B_3_I2C_SDA_2272319: length 16.8
  BOTTOM w0.3: B_3_TB9.3 162.25,22.59 162.25,29.45 164,31.21 B_3_J9.C20
B_3_IRQ_2273337: length 20.6
  BOTTOM w0.3: B_3_J8.C26 119.07,37.6 121.3,37.6 121.95,36.95 121.95,25.45 124.06,23.34 B_3_TB8.4
B_3_VBAT_PVDD: length 11.4
  BOTTOM w0.5: B_3_J9.C3 B_3_J9.C4 161.24,10.88 B_3_TB9.1
B_3_VEN_2272419: length 11.4
  IS2 w0.3: B_3_TB9.5 159.98,22.3 167.39,22.3 B_3_J9.C11
B_4_GND_2272419: length 138.5
  TOP w0.3: 224.11,7.22 B_4_J9.C2 ; B_4_J9.C2 224.11,9.47 ; B_4_J9.C2 222.98,8.34 ; B_4_J9.C2 225.23,8.34 ; B_4_J8.C1 179.51,8.34 ; B_4_J8.C1 178.39,9.47 ; B_4_J8.C1 177.26,8.34 ; B_4_J8.C1 178.39,7.22 ; B_4_J9.C43 227.77,61.69 ; B_4_J9.C43 226.65,60.56 ; B_4_J9.C43 226.65,62.81 ; 225.52,8.34 B_4_J9.C1 ; B_4_J9.C1 227.77,8.34 ; B_4_J9.C1 226.65,7.22 ; B_4_J9.C1 226.65,9.47 ; 215.05,26.39 B_4_TB9.6 217.81,26.39 ; 174.72,8.34 B_4_J8.C2 ; B_4_J8.C2 175.85,9.47 ; B_4_J8.C2 176.97,8.34 ; B_4_J8.C2 175.85,7.22 ; B_4_J9.C45 227.77,64.22 ; B_4_J9.C45 226.65,65.35 ; B_4_J9.C45 226.65,63.1 ; 181.92,28.42 B_4_TB8.6 184.68,28.42
  TOP w0.5: B_4_J9.C44 B_4_J9.C43 ; B_4_J9.C46 B_4_J9.C45
  IS1 w0.3: 181.97,28.42 B_4_TB8.6 184.63,28.42 ; B_4_J8.C2 175.85,9.42 ; B_4_J8.C2 174.77,8.34 ; B_4_J8.C2 176.92,8.34 ; B_4_J8.C2 175.85,7.27 ; B_4_J9.C1 226.65,9.42 ; B_4_J9.C1 225.57,8.34 ; B_4_J9.C1 226.65,7.27 ; B_4_J9.C1 227.72,8.34 ; B_4_J9.C2 225.18,8.34 ; B_4_J9.C2 224.11,7.27 ; B_4_J9.C2 224.11,9.42 ; B_4_J9.C2 223.03,8.34 ; 226.65,60.61 B_4_J9.C43 ; B_4_J9.C43 226.65,62.76 ; B_4_J9.C43 227.72,61.69 ; B_4_J8.C1 179.46,8.34 ; B_4_J8.C1 178.39,7.27 ; B_4_J8.C1 178.39,9.42 ; B_4_J8.C1 177.31,8.34 ; 215.1,26.39 B_4_TB9.6 217.76,26.39 ; B_4_J9.C45 227.72,64.22 ; B_4_J9.C45 226.65,63.15 ; B_4_J9.C45 226.65,65.3
  IS1 w0.5: B_4_J9.C44 B_4_J9.C43 ; B_4_J9.C46 B_4_J9.C45
  IS2 w0.3: B_4_J9.C45 227.72,64.22 ; B_4_J9.C45 226.65,63.15 ; B_4_J9.C45 226.65,65.3 ; B_4_J8.C1 179.46,8.34 ; B_4_J8.C1 178.39,9.42 ; B_4_J8.C1 178.39,7.27 ; B_4_J8.C1 177.31,8.34 ; 217.76,26.39 B_4_TB9.6 215.1,26.39 ; B_4_J9.C1 227.72,8.34 ; B_4_J9.C1 226.65,7.27 ; B_4_J9.C1 226.65,9.42 ; B_4_J9.C1 225.57,8.34 ; 174.77,8.34 B_4_J8.C2 ; B_4_J8.C2 176.92,8.34 ; B_4_J8.C2 175.85,9.42 ; B_4_J8.C2 175.85,7.27 ; 223.03,8.34 B_4_J9.C2 ; B_4_J9.C2 224.11,7.27 ; B_4_J9.C2 224.11,9.42 ; B_4_J9.C2 225.18,8.34 ; B_4_J9.C43 227.72,61.69 ; B_4_J9.C43 226.65,62.76 ; B_4_J9.C43 226.65,60.61 ; 184.63,28.42 B_4_TB8.6 181.97,28.42
  IS2 w0.5: B_4_J9.C44 B_4_J9.C43 ; B_4_J9.C46 B_4_J9.C45
  BOTTOM w0.3: 175.85,7.22 B_4_J8.C2 ; B_4_J8.C2 176.97,8.34 ; B_4_J8.C2 175.85,9.47 ; B_4_J8.C2 174.72,8.34 ; 225.52,8.34 B_4_J9.C1 ; B_4_J9.C1 226.65,7.22 ; B_4_J9.C1 226.65,9.47 ; B_4_J9.C1 227.77,8.34 ; 177.26,8.34 B_4_J8.C1 ; B_4_J8.C1 178.39,7.22 ; B_4_J8.C1 178.39,9.47 ; B_4_J8.C1 179.51,8.34 ; B_4_J9.C43 226.65,62.81 ; B_4_J9.C43 226.65,60.56 ; B_4_J9.C43 227.77,61.69 ; B_4_J9.C45 227.77,64.22 ; B_4_J9.C45 226.65,63.1 ; B_4_J9.C45 226.65,65.35 ; 184.68,28.42 B_4_TB8.6 181.92,28.42 ; B_4_J9.C2 225.23,8.34 ; B_4_J9.C2 222.98,8.34 ; B_4_J9.C2 224.11,7.22 ; B_4_J9.C2 224.11,9.47 ; 217.81,26.39 B_4_TB9.6 215.05,26.39
  BOTTOM w0.5: B_4_J9.C44 B_4_J9.C43 ; B_4_J9.C46 B_4_J9.C45
  vias: v2(175.45,68.05) v2(227.2,67.9)
B_4_I2C_SCL_2272419: length 20.9
  BOTTOM w0.3: B_4_J9.C19 226.65,31.1 225.55,30 222.7,30 221.65,28.95 221.65,21.45 B_4_TB9.2
B_4_I2C_SDA_2272319: length 16.8
  BOTTOM w0.3: B_4_TB9.3 220.25,22.59 220.25,29.45 222,31.21 B_4_J9.C20
B_4_IRQ_2273337: length 20.6
  BOTTOM w0.3: B_4_TB8.4 182.06,23.34 179.95,25.45 179.95,36.95 179.3,37.6 177.07,37.6 B_4_J8.C26
B_4_VBAT_PVDD: length 11.4
  BOTTOM w0.5: B_4_TB9.1 219.24,10.88 B_4_J9.C4 B_4_J9.C3
B_4_VEN_2272419: length 11.4
  IS2 w0.3: B_4_TB9.5 217.98,22.3 225.39,22.3 B_4_J9.C11
B_5_GND_2272419: length 138.5
  TOP w0.3: B_5_J9.C43 284.65,62.81 ; B_5_J9.C43 284.65,60.56 ; B_5_J9.C43 285.77,61.69 ; 284.65,7.22 B_5_J9.C1 ; B_5_J9.C1 284.65,9.47 ; B_5_J9.C1 285.77,8.34 ; B_5_J9.C1 283.52,8.34 ; B_5_J9.C2 282.11,9.47 ; B_5_J9.C2 280.98,8.34 ; B_5_J9.C2 282.11,7.22 ; B_5_J9.C2 283.23,8.34 ; 236.39,7.22 B_5_J8.C1 ; B_5_J8.C1 235.26,8.34 ; B_5_J8.C1 237.51,8.34 ; B_5_J8.C1 236.39,9.47 ; 284.65,63.1 B_5_J9.C45 ; B_5_J9.C45 285.77,64.22 ; B_5_J9.C45 284.65,65.35 ; 232.72,8.34 B_5_J8.C2 ; B_5_J8.C2 233.85,7.22 ; B_5_J8.C2 233.85,9.47 ; B_5_J8.C2 234.97,8.34 ; 242.68,28.42 B_5_TB8.6 239.92,28.42 ; 273.05,26.39 B_5_TB9.6 275.81,26.39
  TOP w0.5: B_5_J9.C44 B_5_J9.C43 ; B_5_J9.C46 B_5_J9.C45
  IS1 w0.3: B_5_J9.C43 285.72,61.69 ; B_5_J9.C43 284.65,62.76 ; B_5_J9.C43 284.65,60.61 ; B_5_J8.C2 233.85,9.42 ; B_5_J8.C2 234.92,8.34 ; B_5_J8.C2 232.77,8.34 ; B_5_J8.C2 233.85,7.27 ; 284.65,7.27 B_5_J9.C1 ; B_5_J9.C1 285.72,8.34 ; B_5_J9.C1 283.57,8.34 ; B_5_J9.C1 284.65,9.42 ; 242.63,28.42 B_5_TB8.6 239.97,28.42 ; 275.76,26.39 B_5_TB9.6 273.1,26.39 ; B_5_J9.C2 282.11,9.42 ; B_5_J9.C2 281.03,8.34 ; B_5_J9.C2 282.11,7.27 ; B_5_J9.C2 283.18,8.34 ; B_5_J8.C1 236.39,9.42 ; B_5_J8.C1 236.39,7.27 ; B_5_J8.C1 235.31,8.34 ; B_5_J8.C1 237.46,8.34 ; B_5_J9.C45 285.72,64.22 ; B_5_J9.C45 284.65,65.3 ; B_5_J9.C45 284.65,63.15
  IS1 w0.5: B_5_J9.C46 B_5_J9.C45 ; B_5_J9.C44 B_5_J9.C43
  IS2 w0.3: 283.57,8.34 B_5_J9.C1 ; B_5_J9.C1 284.65,9.42 ; B_5_J9.C1 284.65,7.27 ; B_5_J9.C1 285.72,8.34 ; 284.65,63.15 B_5_J9.C45 ; B_5_J9.C45 284.65,65.3 ; B_5_J9.C45 285.72,64.22 ; B_5_J8.C1 237.46,8.34 ; B_5_J8.C1 236.39,9.42 ; B_5_J8.C1 235.31,8.34 ; B_5_J8.C1 236.39,7.27 ; 239.97,28.42 B_5_TB8.6 242.63,28.42 ; 233.85,7.27 B_5_J8.C2 ; B_5_J8.C2 233.85,9.42 ; B_5_J8.C2 232.77,8.34 ; B_5_J8.C2 234.92,8.34 ; B_5_J9.C2 283.18,8.34 ; B_5_J9.C2 281.03,8.34 ; B_5_J9.C2 282.11,9.42 ; B_5_J9.C2 282.11,7.27 ; 284.65,60.61 B_5_J9.C43 ; B_5_J9.C43 285.72,61.69 ; B_5_J9.C43 284.65,62.76 ; 273.1,26.39 B_5_TB9.6 275.76,26.39
  IS2 w0.5: B_5_J9.C44 B_5_J9.C43 ; B_5_J9.C46 B_5_J9.C45
  BOTTOM w0.3: B_5_J9.C45 284.65,65.35 ; B_5_J9.C45 285.77,64.22 ; B_5_J9.C45 284.65,63.1 ; 284.65,60.56 B_5_J9.C43 ; B_5_J9.C43 284.65,62.81 ; B_5_J9.C43 285.77,61.69 ; 282.11,7.22 B_5_J9.C2 ; B_5_J9.C2 282.11,9.47 ; B_5_J9.C2 280.98,8.34 ; B_5_J9.C2 283.23,8.34 ; 233.85,7.22 B_5_J8.C2 ; B_5_J8.C2 232.72,8.34 ; B_5_J8.C2 233.85,9.47 ; B_5_J8.C2 234.97,8.34 ; B_5_J8.C1 236.39,9.47 ; B_5_J8.C1 235.26,8.34 ; B_5_J8.C1 237.51,8.34 ; B_5_J8.C1 236.39,7.22 ; B_5_J9.C1 284.65,9.47 ; B_5_J9.C1 283.52,8.34 ; B_5_J9.C1 285.77,8.34 ; B_5_J9.C1 284.65,7.22 ; 275.81,26.39 B_5_TB9.6 273.05,26.39 ; 242.68,28.42 B_5_TB8.6 239.92,28.42
  BOTTOM w0.5: B_5_J9.C44 B_5_J9.C43 ; B_5_J9.C46 B_5_J9.C45
  vias: v2(233.45,68.05) v2(285.2,67.9)
B_5_I2C_SCL_2272419: length 20.9
  BOTTOM w0.3: B_5_J9.C19 284.65,31.1 283.55,30 280.7,30 279.65,28.95 279.65,21.45 B_5_TB9.2
B_5_I2C_SDA_2272319: length 16.8
  BOTTOM w0.3: B_5_J9.C20 280,31.21 278.25,29.45 278.25,22.59 B_5_TB9.3
B_5_IRQ_2273337: length 20.6
  BOTTOM w0.3: B_5_J8.C26 235.07,37.6 237.3,37.6 237.95,36.95 237.95,25.45 240.06,23.34 B_5_TB8.4
B_5_VBAT_PVDD: length 11.4
  BOTTOM w0.5: B_5_TB9.1 277.24,10.88 B_5_J9.C4 B_5_J9.C3
B_5_VEN_2272419: length 11.4
  IS2 w0.3: B_5_J9.C11 283.39,22.3 275.98,22.3 B_5_TB9.5
C_1_GND_2270869: length 82.9
  TOP w0.3: 2.25,100.64 2.25,101.76 ; 2.25,100.64 1.12,100.64 ; 2.25,100.64 2.25,99.51 ; 4.79,95.56 5.91,95.56 ; 4.79,95.56 4.79,94.43 ; 4.79,95.56 4.79,96.68 ; 4.79,95.56 3.66,95.56 ; 2.25,108.25 2.25,109.38 ; 2.25,108.25 1.12,108.25 ; 2.25,108.25 2.25,107.13 ; C_1_J1.6 3.37,90.47 ; C_1_J1.6 1.12,90.47 ; C_1_J1.6 2.25,89.35 ; C_1_J1.6 2.25,91.6 ; 7.82,96.4 C_1_TB5.6 10.58,96.4 ; 40.95,94.37 C_1_TB4.6 43.71,94.37
  IS1 w0.3: 4.79,94.48 4.79,95.56 ; 4.79,95.56 4.79,96.63 ; 4.79,95.56 5.86,95.56 ; 4.79,95.56 3.71,95.56 ; 2.25,89.4 C_1_J1.6 ; C_1_J1.6 2.25,91.55 ; C_1_J1.6 3.32,90.47 ; C_1_J1.6 1.17,90.47 ; 43.66,94.37 C_1_TB4.6 41,94.37 ; 2.25,100.64 2.25,101.71 ; 2.25,100.64 1.17,100.64 ; 2.25,100.64 2.25,99.56 ; 10.53,96.4 C_1_TB5.6 7.87,96.4 ; 2.25,108.25 2.25,109.33 ; 2.25,108.25 1.17,108.25 ; 2.25,108.25 2.25,107.18
  IS2 w0.3: C_1_J1.6 2.25,91.55 ; C_1_J1.6 3.32,90.47 ; C_1_J1.6 2.25,89.4 ; C_1_J1.6 1.17,90.47 ; 10.53,96.4 C_1_TB5.6 7.87,96.4 ; 2.25,100.64 2.25,101.71 ; 2.25,100.64 1.17,100.64 ; 2.25,100.64 2.25,99.56 ; 4.79,114.8 C_1_J1.25 ; C_1_J1.25 4.79,116.95 ; C_1_J1.25 3.71,115.88 ; 4.79,94.48 4.79,95.56 ; 4.79,95.56 4.79,96.63 ; 4.79,95.56 3.71,95.56 ; 4.79,95.56 5.86,95.56 ; 41,94.37 C_1_TB4.6 43.66,94.37 ; 2.25,107.18 2.25,108.25 ; 2.25,108.25 2.25,109.33 ; 2.25,108.25 1.17,108.25
  BOTTOM w0.3: 4.79,96.68 4.79,95.56 5.91,95.56 ; 3.66,115.88 C_1_J1.25 ; C_1_J1.25 4.79,117 ; C_1_J1.25 4.79,114.75 ; 1.12,108.25 2.25,108.25 ; 2.25,108.25 2.25,109.38 ; 2.25,108.25 2.25,107.13 ; 2.25,89.35 C_1_J1.6 ; C_1_J1.6 1.12,90.47 ; C_1_J1.6 3.37,90.47 ; 10.58,96.4 C_1_TB5.6 7.82,96.4 ; 40.95,94.37 C_1_TB4.6 43.71,94.37
  vias: v1(3.52,138.53) v1(3.52,80.53) v1(52.52,138.53) v1(52.52,80.53)
C_1_I2C_SCL_2270949: length 9.8
  BOTTOM w0.3: C_1_J1.5 3.55,89.24 3.55,87.3 4.1,86.75 6.55,86.75 7.06,86.24 C_1_TB5.2
C_1_I2C_SDA_2270933: length 4.8
  BOTTOM w0.3: C_1_TB5.3 5.63,88.78 C_1_J1.3
C_1_IRQ_2270913: length 20
  BOTTOM w0.3: C_1_TB5.4 6.33,91.32 5.85,91.8 1.7,91.8 0.9,92.6 0.9,101.83 C_1_J1.16
C_1_VBAT_PVDD_2271009: length 34.8
  BOTTOM w0.5: 4.79,105.72 6.1,104.4 6.1,99.5 7.1,98.5 10.75,98.5 12.55,96.7 12.55,85.5 10.75,83.7 C_1_TB5.1 6.48,83.7 4.79,85.39 C_1_J1.1
C_1_VEN_2270923: length 17.4
  BOTTOM w0.3: C_1_TB5.5 8.76,94.3 4.2,94.3 3.55,94.95 3.55,104.41 2.25,105.72
C_2_GND_2270869: length 82.9
  TOP w0.3: 59.12,90.47 C_2_J1.6 ; C_2_J1.6 60.25,89.35 ; C_2_J1.6 60.25,91.6 ; C_2_J1.6 61.37,90.47 ; 59.12,100.64 60.25,100.64 ; 60.25,100.64 60.25,101.76 ; 60.25,100.64 60.25,99.51 ; 62.79,95.56 62.79,96.68 ; 62.79,95.56 61.66,95.56 ; 62.79,95.56 63.91,95.56 ; 62.79,95.56 62.79,94.43 ; 60.25,108.25 60.25,109.38 ; 60.25,108.25 60.25,107.13 ; 60.25,108.25 59.12,108.25 ; 68.58,96.4 C_2_TB5.6 65.82,96.4 ; 101.71,94.37 C_2_TB4.6 98.95,94.37
  IS1 w0.3: 62.79,95.56 62.79,96.63 ; 62.79,95.56 62.79,94.48 ; 62.79,95.56 63.86,95.56 ; 62.79,95.56 61.71,95.56 ; 60.25,99.56 60.25,100.64 ; 60.25,100.64 60.25,101.71 ; 60.25,100.64 59.17,100.64 ; C_2_J1.6 60.25,91.55 ; C_2_J1.6 60.25,89.4 ; C_2_J1.6 59.17,90.47 ; C_2_J1.6 61.32,90.47 ; 59.17,108.25 60.25,108.25 ; 60.25,108.25 60.25,109.33 ; 60.25,108.25 60.25,107.18 ; 68.53,96.4 C_2_TB5.6 65.87,96.4 ; 101.66,94.37 C_2_TB4.6 99,94.37
  IS2 w0.3: 60.25,89.4 C_2_J1.6 ; C_2_J1.6 60.25,91.55 ; C_2_J1.6 59.17,90.47 ; C_2_J1.6 61.32,90.47 ; 101.66,94.37 C_2_TB4.6 99,94.37 ; 61.71,115.88 C_2_J1.25 ; C_2_J1.25 62.79,116.95 ; C_2_J1.25 62.79,114.8 ; 60.25,100.64 60.25,101.71 ; 60.25,100.64 59.17,100.64 ; 60.25,100.64 60.25,99.56 ; 62.79,95.56 62.79,96.63 ; 62.79,95.56 62.79,94.48 ; 62.79,95.56 63.86,95.56 ; 62.79,95.56 61.71,95.56 ; 65.87,96.4 C_2_TB5.6 68.53,96.4 ; 60.25,107.18 60.25,108.25 ; 60.25,108.25 60.25,109.33 ; 60.25,108.25 59.17,108.25
  BOTTOM w0.3: 65.82,96.4 C_2_TB5.6 68.58,96.4 ; 59.12,108.25 60.25,108.25 ; 60.25,108.25 60.25,107.13 ; 60.25,108.25 60.25,109.38 ; 62.79,96.68 62.79,95.56 63.91,95.56 ; 62.79,114.75 C_2_J1.25 ; C_2_J1.25 61.66,115.88 ; C_2_J1.25 62.79,117 ; C_2_J1.6 61.37,90.47 ; C_2_J1.6 59.12,90.47 ; C_2_J1.6 60.25,89.35 ; 101.71,94.37 C_2_TB4.6 98.95,94.37
  vias: v1(61.52,138.53) v1(61.52,80.53) v1(110.52,138.53) v1(110.52,80.53)
C_2_I2C_SCL_2270949: length 9.8
  BOTTOM w0.3: C_2_TB5.2 65.06,86.24 64.55,86.75 62.1,86.75 61.55,87.3 61.55,89.24 C_2_J1.5
C_2_I2C_SDA_2270933: length 4.8
  BOTTOM w0.3: C_2_J1.3 63.63,88.78 C_2_TB5.3
C_2_IRQ_2270913: length 20
  BOTTOM w0.3: C_2_TB5.4 64.33,91.32 63.85,91.8 59.7,91.8 58.9,92.6 58.9,101.83 C_2_J1.16
C_2_VBAT_PVDD_2271009: length 34.8
  BOTTOM w0.5: C_2_J1.1 62.79,85.39 64.48,83.7 C_2_TB5.1 68.75,83.7 70.55,85.5 70.55,96.7 68.75,98.5 65.1,98.5 64.1,99.5 64.1,104.4 62.79,105.72
C_2_VEN_2270923: length 17.4
  BOTTOM w0.3: C_2_TB5.5 66.76,94.3 62.2,94.3 61.55,94.95 61.55,104.41 60.25,105.72
C_3_GND_2270869: length 82.9
  TOP w0.3: 118.25,89.35 C_3_J1.6 ; C_3_J1.6 117.12,90.47 ; C_3_J1.6 119.37,90.47 ; C_3_J1.6 118.25,91.6 ; 156.95,94.37 C_3_TB4.6 159.71,94.37 ; 119.66,95.56 120.79,95.56 ; 120.79,95.56 121.91,95.56 ; 120.79,95.56 120.79,96.68 ; 120.79,95.56 120.79,94.43 ; 123.82,96.4 C_3_TB5.6 126.58,96.4 ; 118.25,107.13 118.25,108.25 ; 118.25,108.25 118.25,109.38 ; 118.25,108.25 117.12,108.25 ; 117.12,100.64 118.25,100.64 ; 118.25,100.64 118.25,99.51 ; 118.25,100.64 118.25,101.76
  IS1 w0.3: 117.17,108.25 118.25,108.25 ; 118.25,108.25 118.25,107.18 ; 118.25,108.25 118.25,109.33 ; 117.17,100.64 118.25,100.64 ; 118.25,100.64 118.25,101.71 ; 118.25,100.64 118.25,99.56 ; 120.79,94.48 120.79,95.56 ; 120.79,95.56 119.71,95.56 ; 120.79,95.56 120.79,96.63 ; 120.79,95.56 121.86,95.56 ; 117.17,90.47 C_3_J1.6 ; C_3_J1.6 119.32,90.47 ; C_3_J1.6 118.25,89.4 ; C_3_J1.6 118.25,91.55 ; 157,94.37 C_3_TB4.6 159.66,94.37 ; 123.87,96.4 C_3_TB5.6 126.53,96.4
  IS2 w0.3: 118.25,89.4 C_3_J1.6 ; C_3_J1.6 117.17,90.47 ; C_3_J1.6 119.32,90.47 ; C_3_J1.6 118.25,91.55 ; 126.53,96.4 C_3_TB5.6 123.87,96.4 ; 118.25,100.64 118.25,101.71 ; 118.25,100.64 117.17,100.64 ; 118.25,100.64 118.25,99.56 ; 117.17,108.25 118.25,108.25 ; 118.25,108.25 118.25,107.18 ; 118.25,108.25 118.25,109.33 ; 159.66,94.37 C_3_TB4.6 157,94.37 ; C_3_J1.25 120.79,116.95 ; C_3_J1.25 120.79,114.8 ; C_3_J1.25 119.71,115.88 ; 120.79,95.56 120.79,96.63 ; 120.79,95.56 120.79,94.48 ; 120.79,95.56 121.86,95.56 ; 120.79,95.56 119.71,95.56
  BOTTOM w0.3: 118.25,89.35 C_3_J1.6 ; C_3_J1.6 117.12,90.47 ; C_3_J1.6 119.37,90.47 ; 123.82,96.4 C_3_TB5.6 126.58,96.4 ; 118.25,108.25 118.25,109.38 ; 118.25,108.25 117.12,108.25 ; 118.25,108.25 118.25,107.13 ; 120.79,114.75 C_3_J1.25 ; C_3_J1.25 119.66,115.88 ; C_3_J1.25 120.79,117 ; 156.95,94.37 C_3_TB4.6 159.71,94.37 ; 121.91,95.56 120.79,95.56 120.79,96.68
  vias: v1(119.52,138.53) v1(119.52,80.53) v1(168.52,138.53) v1(168.52,80.53)
C_3_I2C_SCL_2270949: length 9.8
  BOTTOM w0.3: C_3_TB5.2 123.06,86.24 122.55,86.75 120.1,86.75 119.55,87.3 119.55,89.24 C_3_J1.5
C_3_I2C_SDA_2270933: length 4.8
  BOTTOM w0.3: C_3_J1.3 121.63,88.78 C_3_TB5.3
C_3_IRQ_2270913: length 20
  BOTTOM w0.3: C_3_J1.16 116.9,101.83 116.9,92.6 117.7,91.8 121.85,91.8 122.33,91.32 C_3_TB5.4
C_3_VBAT_PVDD_2271009: length 34.8
  BOTTOM w0.5: C_3_J1.1 120.79,85.39 122.48,83.7 C_3_TB5.1 126.75,83.7 128.55,85.5 128.55,96.7 126.75,98.5 123.1,98.5 122.1,99.5 122.1,104.4 120.79,105.72
C_3_VEN_2270923: length 17.4
  BOTTOM w0.3: C_3_TB5.5 124.76,94.3 120.2,94.3 119.55,94.95 119.55,104.41 118.25,105.72
C_4_GND_2270869: length 82.9
  TOP w0.3: 176.25,107.13 176.25,108.25 ; 176.25,108.25 175.12,108.25 ; 176.25,108.25 176.25,109.38 ; 175.12,90.47 C_4_J1.6 ; C_4_J1.6 176.25,91.6 ; C_4_J1.6 176.25,89.35 ; C_4_J1.6 177.37,90.47 ; 178.79,95.56 178.79,96.68 ; 178.79,95.56 178.79,94.43 ; 178.79,95.56 177.66,95.56 ; 178.79,95.56 179.91,95.56 ; 176.25,100.64 176.25,101.76 ; 176.25,100.64 175.12,100.64 ; 176.25,100.64 176.25,99.51 ; 214.95,94.37 C_4_TB4.6 217.71,94.37 ; 181.82,96.4 C_4_TB5.6 184.58,96.4
  IS1 w0.3: 178.79,95.56 178.79,96.63 ; 178.79,95.56 179.86,95.56 ; 178.79,95.56 177.71,95.56 ; 178.79,95.56 178.79,94.48 ; 175.17,90.47 C_4_J1.6 ; C_4_J1.6 176.25,91.55 ; C_4_J1.6 176.25,89.4 ; C_4_J1.6 177.32,90.47 ; 176.25,99.56 176.25,100.64 ; 176.25,100.64 175.17,100.64 ; 176.25,100.64 176.25,101.71 ; 176.25,107.18 176.25,108.25 ; 176.25,108.25 175.17,108.25 ; 176.25,108.25 176.25,109.33 ; 217.66,94.37 C_4_TB4.6 215,94.37 ; 184.53,96.4 C_4_TB5.6 181.87,96.4
  IS2 w0.3: C_4_J1.6 176.25,91.55 ; C_4_J1.6 177.32,90.47 ; C_4_J1.6 175.17,90.47 ; C_4_J1.6 176.25,89.4 ; 178.79,95.56 179.86,95.56 ; 178.79,95.56 178.79,94.48 ; 178.79,95.56 177.71,95.56 ; 178.79,95.56 178.79,96.63 ; C_4_J1.25 178.79,116.95 ; C_4_J1.25 178.79,114.8 ; C_4_J1.25 177.71,115.88 ; 176.25,108.25 176.25,109.33 ; 176.25,108.25 175.17,108.25 ; 176.25,108.25 176.25,107.18 ; 175.17,100.64 176.25,100.64 ; 176.25,100.64 176.25,101.71 ; 176.25,100.64 176.25,99.56 ; 181.87,96.4 C_4_TB5.6 184.53,96.4 ; 217.66,94.37 C_4_TB4.6 215,94.37
  BOTTOM w0.3: 176.25,89.35 C_4_J1.6 ; C_4_J1.6 177.37,90.47 ; C_4_J1.6 175.12,90.47 ; 177.66,115.88 C_4_J1.25 ; C_4_J1.25 178.79,114.75 ; C_4_J1.25 178.79,117 ; 214.95,94.37 C_4_TB4.6 217.71,94.37 ; 179.91,95.56 178.79,95.56 178.79,96.68 ; 176.25,108.25 176.25,109.38 ; 176.25,108.25 175.12,108.25 ; 176.25,108.25 176.25,107.13 ; 184.58,96.4 C_4_TB5.6 181.82,96.4
  vias: v1(177.52,138.53) v1(177.52,80.53) v1(226.52,138.53) v1(226.52,80.53)
C_4_I2C_SCL_2270949: length 9.8
  BOTTOM w0.3: C_4_TB5.2 181.06,86.24 180.55,86.75 178.1,86.75 177.55,87.3 177.55,89.24 C_4_J1.5
C_4_I2C_SDA_2270933: length 4.8
  BOTTOM w0.3: C_4_J1.3 179.63,88.78 C_4_TB5.3
C_4_IRQ_2270913: length 20
  BOTTOM w0.3: C_4_TB5.4 180.33,91.32 179.85,91.8 175.7,91.8 174.9,92.6 174.9,101.83 C_4_J1.16
C_4_VBAT_PVDD_2271009: length 34.8
  BOTTOM w0.5: 178.79,105.72 180.1,104.4 180.1,99.5 181.1,98.5 184.75,98.5 186.55,96.7 186.55,85.5 184.75,83.7 C_4_TB5.1 180.48,83.7 178.79,85.39 C_4_J1.1
C_4_VEN_2270923: length 17.4
  BOTTOM w0.3: 176.25,105.72 177.55,104.41 177.55,94.95 178.2,94.3 182.76,94.3 C_4_TB5.5
C_5_GND_2270869: length 82.9
  TOP w0.3: 233.12,100.64 234.25,100.64 ; 234.25,100.64 234.25,99.51 ; 234.25,100.64 234.25,101.76 ; 275.71,94.37 C_5_TB4.6 272.95,94.37 ; 235.66,95.56 236.79,95.56 ; 236.79,95.56 236.79,96.68 ; 236.79,95.56 237.91,95.56 ; 236.79,95.56 236.79,94.43 ; 233.12,108.25 234.25,108.25 ; 234.25,108.25 234.25,109.38 ; 234.25,108.25 234.25,107.13 ; C_5_J1.6 234.25,91.6 ; C_5_J1.6 235.37,90.47 ; C_5_J1.6 233.12,90.47 ; C_5_J1.6 234.25,89.35 ; 239.82,96.4 C_5_TB5.6 242.58,96.4
  IS1 w0.3: 233.17,100.64 234.25,100.64 ; 234.25,100.64 234.25,99.56 ; 234.25,100.64 234.25,101.71 ; 235.71,95.56 236.79,95.56 ; 236.79,95.56 237.86,95.56 ; 236.79,95.56 236.79,94.48 ; 236.79,95.56 236.79,96.63 ; 234.25,108.25 234.25,109.33 ; 234.25,108.25 233.17,108.25 ; 234.25,108.25 234.25,107.18 ; 234.25,89.4 C_5_J1.6 ; C_5_J1.6 233.17,90.47 ; C_5_J1.6 235.32,90.47 ; C_5_J1.6 234.25,91.55 ; 273,94.37 C_5_TB4.6 275.66,94.37 ; 239.87,96.4 C_5_TB5.6 242.53,96.4
  IS2 w0.3: C_5_J1.25 236.79,116.95 ; C_5_J1.25 235.71,115.88 ; C_5_J1.25 236.79,114.8 ; 234.25,89.4 C_5_J1.6 ; C_5_J1.6 234.25,91.55 ; C_5_J1.6 235.32,90.47 ; C_5_J1.6 233.17,90.47 ; 234.25,107.18 234.25,108.25 ; 234.25,108.25 234.25,109.33 ; 234.25,108.25 233.17,108.25 ; 235.71,95.56 236.79,95.56 ; 236.79,95.56 236.79,96.63 ; 236.79,95.56 236.79,94.48 ; 236.79,95.56 237.86,95.56 ; 273,94.37 C_5_TB4.6 275.66,94.37 ; 242.53,96.4 C_5_TB5.6 239.87,96.4 ; 234.25,99.56 234.25,100.64 ; 234.25,100.64 234.25,101.71 ; 234.25,100.64 233.17,100.64
  BOTTOM w0.3: 236.79,96.68 236.79,95.56 237.91,95.56 ; 275.71,94.37 C_5_TB4.6 272.95,94.37 ; 239.82,96.4 C_5_TB5.6 242.58,96.4 ; 235.66,115.88 C_5_J1.25 ; C_5_J1.25 236.79,117 ; C_5_J1.25 236.79,114.75 ; 234.25,89.35 C_5_J1.6 ; C_5_J1.6 233.12,90.47 ; C_5_J1.6 235.37,90.47 ; 233.12,108.25 234.25,108.25 ; 234.25,108.25 234.25,107.13 ; 234.25,108.25 234.25,109.38
  vias: v1(235.52,138.53) v1(235.52,80.53) v1(284.52,138.53) v1(284.52,80.53)
C_5_I2C_SCL_2270949: length 9.8
  BOTTOM w0.3: C_5_J1.5 235.55,89.24 235.55,87.3 236.1,86.75 238.55,86.75 239.06,86.24 C_5_TB5.2
C_5_I2C_SDA_2270933: length 4.8
  BOTTOM w0.3: C_5_J1.3 237.63,88.78 C_5_TB5.3
C_5_IRQ_2270913: length 20
  BOTTOM w0.3: C_5_TB5.4 238.33,91.32 237.85,91.8 233.7,91.8 232.9,92.6 232.9,101.83 C_5_J1.16
C_5_VBAT_PVDD_2271009: length 34.8
  BOTTOM w0.5: 236.79,105.72 238.1,104.4 238.1,99.5 239.1,98.5 242.75,98.5 244.55,96.7 244.55,85.5 242.75,83.7 C_5_TB5.1 238.48,83.7 236.79,85.39 C_5_J1.1
C_5_VEN_2270923: length 17.4
  BOTTOM w0.3: C_5_TB5.5 240.76,94.3 236.2,94.3 235.55,94.95 235.55,104.41 234.25,105.72

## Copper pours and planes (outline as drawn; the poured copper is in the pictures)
(no net) on TOP: 45.75,169.5 5.75,169.5 5.75,193 24.95,193 24.95,194.25 25.4,194.7 26,194.7 26.45,194.25 26.45,193 45.75,193 ; 4 cut-outs
(no net) on TOP: 93,169.5 53,169.5 53,193 72.2,193 72.2,194.25 72.65,194.7 73.25,194.7 73.7,194.25 73.7,193 93,193 ; 4 cut-outs
(no net) on TOP: 187.5,169.5 147.5,169.5 147.5,193 166.7,193 166.7,194.25 167.15,194.7 167.75,194.7 168.2,194.25 168.2,193 187.5,193 ; 4 cut-outs
(no net) on TOP: 140.25,169.5 100.25,169.5 100.25,193 119.45,193 119.45,194.25 119.9,194.7 120.5,194.7 120.95,194.25 120.95,193 140.25,193 ; 4 cut-outs
(no net) on TOP: 234.75,169.5 194.75,169.5 194.75,193 213.95,193 213.95,194.25 214.4,194.7 215,194.7 215.45,194.25 215.45,193 234.75,193 ; 4 cut-outs
(no net) on TOP: 282,169.5 242,169.5 242,193 261.2,193 261.2,194.25 261.65,194.7 262.25,194.7 262.7,194.25 262.7,193 282,193 ; 4 cut-outs
(no net) on TOP, IS1: 287.5,80.05 284.94,77.5 235.01,77.5 232.5,80 232.5,159 235,161.5 284.95,161.5 287.5,158.95 ; 1 cut-out
(no net) on TOP, IS1: 171.5,80.05 168.94,77.5 119.01,77.5 116.5,80 116.5,159 119,161.5 168.95,161.5 171.5,158.95 ; 1 cut-out
(no net) on TOP, IS1: 55.5,80.05 52.94,77.5 3.01,77.5 0.5,80 0.5,159 3,161.5 52.95,161.5 55.5,158.95 ; 1 cut-out
(no net) on TOP, IS1: 113.5,80.05 110.94,77.5 61.01,77.5 58.5,80 58.5,159 61,161.5 110.95,161.5 113.5,158.95 ; 1 cut-out
(no net) on TOP, IS1: 229.5,80.05 226.94,77.5 177.01,77.5 174.5,80 174.5,159 177,161.5 226.95,161.5 229.5,158.95 ; 1 cut-out
(no net) on TOP, IS1, IS2: 112,5.5 98.7,5.5 98.7,8.65 97.85,9.5 72.55,9.5 71.7,8.65 71.7,0.5 58.5,0.5 58.5,68.5 58.51,68.5 60.25,68.5 60.25,29.45 110.25,29.45 110.25,68.5 111.99,68.5 112,68.5
